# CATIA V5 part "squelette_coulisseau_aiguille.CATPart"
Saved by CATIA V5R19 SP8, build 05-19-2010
Part number: squelette_coulisseau_aiguille
Publications: "Plan.1", "Plan.2"
Bounding box of the stored display mesh (mm): x -6 to 0, y 0 to 6.5, z -84 to -84
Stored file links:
  C:\Users\ThinkMotion\Desktop\EU_thinkMotion\iao\IAO_MMS_Groupe3\pmayet\pmayet_avant_optimisation\pmayet_avant_optimisation\squelette_coulisseau_aiguille.CATPart
  C:\Users\ThinkMotion\Desktop\EU_thinkMotion\iao\IAO_MMS_Groupe3\pmayet\pmayet_avant_optimisation\pmayet_avant_optimisation\squelette.CATProduct
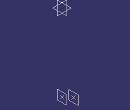
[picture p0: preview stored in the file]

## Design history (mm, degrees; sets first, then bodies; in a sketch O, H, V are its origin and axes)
Set1
  Point1 "PointB": linked copy from another document
  Point2 "Point_origine_aiguille": linked copy from another document
Set2
  Plane1: type OffsetPt, RefPlane yz-plane, RefPoint Point1
  Plane2: type OffsetPt, RefPlane yz-plane, RefPoint Point2
Body1 (main body)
